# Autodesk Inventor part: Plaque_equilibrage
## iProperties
Created: 2011-01
Part Number: Plaque_equilibrage
Document SubType Name: Modeling
Designer: eric
Density: 1 g/cm^3
Mass: 3.16783 g
Surface Area: 35.2804 cm^2
Volume: 3.16783 cm^3
Author: eric
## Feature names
1. Base1
